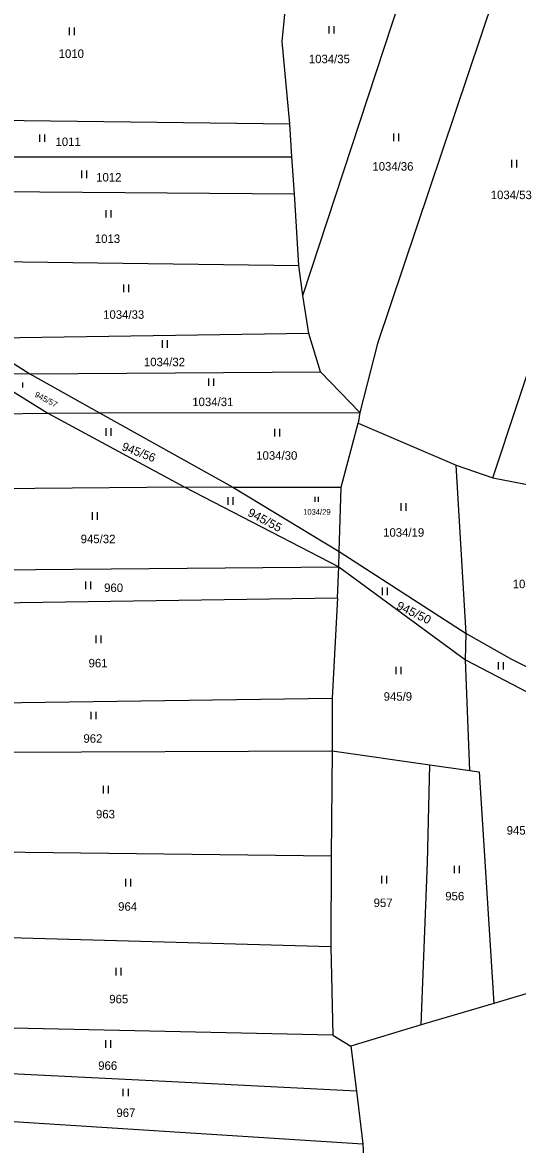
# Model space of a CAD drawing. Extents: x -820420 to -815896, y -1105820 to -1103643.
# Drawn here: x -818231 to -818131.9, y -1104803.9 to -1104579.4 of the extents above; entities that cross this region are included whole.
import ezdxf
from ezdxf.enums import TextEntityAlignment as Align

# ---------------------------------------------------------------- set-up
doc = ezdxf.new("R2010")
doc.units = 0
doc.header["$LTSCALE"] = 0.68
doc.layers.add('1', color=7, linetype='Continuous', lineweight=25)
doc.layers.add('3', color=7, linetype='Continuous', lineweight=25)
doc.layers.add('2', color=7, linetype='Continuous')

msp = doc.modelspace()

# ---------------------------------------------------------------- linework, layer by layer
at = {"layer": '1'}
for p, q in [((-818174.88, -1104634.05), (-818152, -1104564.59)), ((-818133.7, -1104565.65), (-818159.92, -1104643.63)), ((-818178.97, -1104583.19), (-818177.63, -1104569.05)), ((-818177.49, -1104599.69), (-818178.97, -1104583.19)), ((-818264.42, -1104598.63), (-818177.49, -1104599.69)), ((-818177.09, -1104606.27), (-818177.49, -1104599.69)), ((-818136.83, -1104670.54), (-818113.66, -1104600.35)), ((-818262.2, -1104606.27), (-818177.09, -1104606.27)), ((-818176.54, -1104613.71), (-818177.09, -1104606.27)), ((-818260.78, -1104613), (-818176.54, -1104613.71)), ((-818175.65, -1104628.02), (-818176.54, -1104613.71)), ((-818258.64, -1104626.97), (-818175.65, -1104628.02)), ((-818174.88, -1104634.05), (-818175.65, -1104628.02)), ((-818173.65, -1104641.67), (-818174.88, -1104634.05)), ((-818173.65, -1104641.67), (-818240.67, -1104642.61)), ((-818171.33, -1104649.31), (-818173.65, -1104641.67)), ((-818240.67, -1104642.61), (-818229.46, -1104649.71)), ((-818159.92, -1104643.63), (-818163.42, -1104657.44)), ((-818238.7, -1104649.63), (-818225.89, -1104657.59)), ((-818238.7, -1104649.63), (-818229.46, -1104649.71)), ((-818229.46, -1104649.71), (-818171.33, -1104649.31)), ((-818229.46, -1104649.71), (-818215.52, -1104657.49)), ((-818163.42, -1104657.44), (-818171.33, -1104649.31)), ((-818253.9, -1104657.91), (-818225.89, -1104657.59)), ((-818225.89, -1104657.59), (-818215.52, -1104657.49)), ((-818225.89, -1104657.59), (-818198.6, -1104672.29)), ((-818215.52, -1104657.49), (-818163.42, -1104657.44)), ((-818215.52, -1104657.49), (-818188.84, -1104672.38)), ((-818163.42, -1104657.44), (-818163.76, -1104659.59)), ((-818167.16, -1104672.38), (-818163.76, -1104659.59)), ((-818163.76, -1104659.59), (-818144.15, -1104667.98)), ((-818142.19, -1104701.67), (-818144.15, -1104667.98)), ((-818144.15, -1104667.98), (-818136.83, -1104670.54)), ((-818136.83, -1104670.54), (-818108.78, -1104675.85)), ((-818254.67, -1104672.84), (-818198.6, -1104672.29)), ((-818198.6, -1104672.29), (-818188.84, -1104672.38)), ((-818198.6, -1104672.29), (-818167.67, -1104688.35)), ((-818188.84, -1104672.38), (-818167.16, -1104672.38)), ((-818188.84, -1104672.38), (-818167.57, -1104685.27)), ((-818167.57, -1104685.27), (-818167.16, -1104672.38)), ((-818167.67, -1104688.35), (-818167.57, -1104685.27)), ((-818167.57, -1104685.27), (-818142.19, -1104701.67)), ((-818262.87, -1104689.1), (-818167.67, -1104688.35)), ((-818167.93, -1104694.51), (-818167.67, -1104688.35)), ((-818167.67, -1104688.35), (-818142.3, -1104706.93)), ((-818269.59, -1104696.04), (-818167.93, -1104694.51)), ((-818167.93, -1104694.51), (-818168.98, -1104714.58)), ((-818142.3, -1104706.93), (-818142.19, -1104701.67)), ((-818142.19, -1104701.67), (-818133.07, -1104706.81)), ((-818142.3, -1104706.93), (-818122.39, -1104717.32)), ((-818141.44, -1104729.08), (-818142.3, -1104706.93)), ((-818133.07, -1104706.81), (-818121.19, -1104712.84)), ((-818268.38, -1104716.03), (-818168.98, -1104714.58)), ((-818168.98, -1104714.58), (-818169.01, -1104725.11)), ((-818268.58, -1104725.5), (-818169.01, -1104725.11)), ((-818169.01, -1104725.11), (-818169.16, -1104746.19)), ((-818169.01, -1104725.11), (-818149.44, -1104727.93)), ((-818149.92, -1104747.49), (-818149.44, -1104727.93)), ((-818149.44, -1104727.93), (-818141.44, -1104729.08)), ((-818141.44, -1104729.08), (-818139.55, -1104729.35)), ((-818139.55, -1104729.35), (-818136.65, -1104775.68)), ((-818169.16, -1104746.19), (-818254.54, -1104745.22)), ((-818169.16, -1104746.19), (-818169.23, -1104764.29)), ((-818151.16, -1104779.92), (-818149.92, -1104747.49)), ((-818261.78, -1104761.72), (-818169.23, -1104764.29)), ((-818169.23, -1104764.29), (-818168.88, -1104782.03)), ((-818112.73, -1104768.55), (-818136.65, -1104775.68)), ((-818136.65, -1104775.68), (-818151.16, -1104779.92)), ((-818168.88, -1104782.03), (-818261.57, -1104779.95)), ((-818151.16, -1104779.92), (-818165.23, -1104784.19)), ((-818168.88, -1104782.03), (-818165.23, -1104784.19)), ((-818165.23, -1104784.19), (-818164.11, -1104793.2)), ((-818205.03, -1104791.15), (-818266.71, -1104788.12)), ((-818164.11, -1104793.2), (-818205.03, -1104791.15)), ((-818164.11, -1104793.2), (-818162.87, -1104803.73)), ((-818275, -1104796.63), (-818162.87, -1104803.73)), ((-818162.87, -1104803.73), (-818161.83, -1104821.84))]:
    msp.add_line(p, q, dxfattribs=at)
at = {"layer": '3'}
for p, q in [((-818221.571, -1104581.93), (-818221.571, -1104580.43)), ((-818220.57, -1104581.93), (-818220.57, -1104580.43)), ((-818169.621, -1104581.65), (-818169.621, -1104580.15)), ((-818168.62, -1104581.65), (-818168.62, -1104580.15)), ((-818227.511, -1104603.31), (-818227.511, -1104601.81)), ((-818226.51, -1104603.31), (-818226.51, -1104601.81)), ((-818156.681, -1104603.15), (-818156.681, -1104601.65)), ((-818155.68, -1104603.15), (-818155.68, -1104601.65)), ((-818133.011, -1104608.41), (-818133.011, -1104606.91)), ((-818132.01, -1104608.41), (-818132.01, -1104606.91)), ((-818219.111, -1104610.55), (-818219.111, -1104609.05)), ((-818218.11, -1104610.55), (-818218.11, -1104609.05)), ((-818214.201, -1104618.44), (-818214.201, -1104616.94)), ((-818213.2, -1104618.44), (-818213.2, -1104616.94)), ((-818210.711, -1104633.36), (-818210.711, -1104631.86)), ((-818209.71, -1104633.36), (-818209.71, -1104631.86)), ((-818202.951, -1104644.48), (-818202.951, -1104642.98)), ((-818201.95, -1104644.48), (-818201.95, -1104642.98)), ((-818193.641, -1104652.11), (-818193.641, -1104650.61)), ((-818192.64, -1104652.11), (-818192.64, -1104650.61)), ((-818230.902, -1104652.44), (-818230.902, -1104651.435)), ((-818214.201, -1104662.11), (-818214.201, -1104660.61)), ((-818213.2, -1104662.11), (-818213.2, -1104660.61)), ((-818180.451, -1104662.24), (-818180.451, -1104660.74)), ((-818179.45, -1104662.24), (-818179.45, -1104660.74)), ((-818189.791, -1104675.89), (-818189.791, -1104674.39)), ((-818188.79, -1104675.89), (-818188.79, -1104674.39)), ((-818172.392, -1104675.31), (-818172.392, -1104674.305)), ((-818171.722, -1104675.31), (-818171.722, -1104674.305)), ((-818216.941, -1104678.89), (-818216.941, -1104677.39)), ((-818215.94, -1104678.89), (-818215.94, -1104677.39)), ((-818155.191, -1104677.11), (-818155.191, -1104675.61)), ((-818154.19, -1104677.11), (-818154.19, -1104675.61)), ((-818218.271, -1104692.78), (-818218.271, -1104691.28)), ((-818217.27, -1104692.78), (-818217.27, -1104691.28)), ((-818158.891, -1104693.96), (-818158.891, -1104692.46)), ((-818157.89, -1104693.96), (-818157.89, -1104692.46)), ((-818216.201, -1104703.57), (-818216.201, -1104702.07)), ((-818215.2, -1104703.57), (-818215.2, -1104702.07)), ((-818156.201, -1104709.8), (-818156.201, -1104708.3)), ((-818155.2, -1104709.8), (-818155.2, -1104708.3)), ((-818135.691, -1104708.88), (-818135.691, -1104707.38)), ((-818134.69, -1104708.88), (-818134.69, -1104707.38)), ((-818217.231, -1104718.8), (-818217.231, -1104717.3)), ((-818216.23, -1104718.8), (-818216.23, -1104717.3)), ((-818214.721, -1104733.64), (-818214.721, -1104732.14)), ((-818213.72, -1104733.64), (-818213.72, -1104732.14)), ((-818144.531, -1104749.61), (-818144.531, -1104748.11)), ((-818143.53, -1104749.61), (-818143.53, -1104748.11)), ((-818210.291, -1104752.27), (-818210.291, -1104750.77)), ((-818209.29, -1104752.27), (-818209.29, -1104750.77)), ((-818159.031, -1104751.65), (-818159.031, -1104750.15)), ((-818158.03, -1104751.65), (-818158.03, -1104750.15)), ((-818212.211, -1104770.05), (-818212.211, -1104768.55)), ((-818211.21, -1104770.05), (-818211.21, -1104768.55)), ((-818214.281, -1104784.54), (-818214.281, -1104783.04)), ((-818213.28, -1104784.54), (-818213.28, -1104783.04)), ((-818210.781, -1104794.24), (-818210.781, -1104792.74)), ((-818209.78, -1104794.24), (-818209.78, -1104792.74))]:
    msp.add_line(p, q, dxfattribs=at)

# ---------------------------------------------------------------- texts
at = {"layer": '2'}
for s, height, p in [('1010', 1.7, (-818221.19, -1104586.495)), ('1034/35', 1.7, (-818169.549, -1104587.565)), ('1011', 1.7, (-818221.83, -1104604.125)), ('1034/36', 1.7, (-818156.829, -1104609.055)), ('1012', 1.7, (-818213.69, -1104611.235)), ('1034/53', 1.7, (-818133.149, -1104614.755)), ('1013', 1.7, (-818213.95, -1104623.525)), ('1034/33', 1.7, (-818210.709, -1104638.695)), ('1034/32', 1.7, (-818202.549, -1104648.185)), ('1034/31', 1.7, (-818192.869, -1104656.165)), ('1034/30', 1.7, (-818180.069, -1104666.895)), ('1034/29', 1.139, (-818172.049, -1104677.914)), ('945/32', 1.7, (-818215.84, -1104683.595)), ('1034/19', 1.7, (-818154.679, -1104682.295)), ('1034/18', 1.7, (-818128.749, -1104692.595)), ('960', 1.7, (-818212.729, -1104693.355)), ('961', 1.7, (-818215.839, -1104708.435)), ('945/9', 1.7, (-818155.84, -1104715.105)), ('962', 1.7, (-818216.869, -1104723.515)), ('963', 1.7, (-818214.359, -1104738.645)), ('945/8', 1.7, (-818131.22, -1104741.895)), ('956', 1.7, (-818144.459, -1104755.055)), ('964', 1.7, (-818209.919, -1104757.125)), ('957', 1.7, (-818158.799, -1104756.385)), ('965', 1.7, (-818211.699, -1104775.645)), ('966', 1.7, (-818213.909, -1104788.955)), ('967', 1.7, (-818210.269, -1104798.385))]:
    msp.add_text(s, height=height, dxfattribs=at).set_placement(p, align=Align.CENTER)
at = {"layer": '2', "width": 1.05}
for s, height, rotation, p in [('945/57', 1.139, 332, (-818226.4874, -1104655.3237)), ('945/55', 1.7, 332, (-818182.8461, -1104679.7025)), ('945/50', 1.7, 334, (-818153.0056, -1104698.2541))]:
    msp.add_text(s, height=height, rotation=rotation, dxfattribs=at).set_placement(p, align=Align.CENTER)
at = {"layer": '2'}
msp.add_text('945/56', height=1.7, rotation=339, dxfattribs=at).set_placement((-818207.9871, -1104666.1656), align=Align.CENTER)

doc.saveas('drawing.dxf')
